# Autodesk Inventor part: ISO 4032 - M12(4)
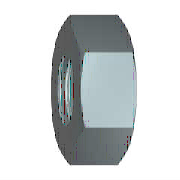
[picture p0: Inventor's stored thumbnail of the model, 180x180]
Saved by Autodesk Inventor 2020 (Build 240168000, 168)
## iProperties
Created: 2019-01
Part Number: ISO 4032 - M12(4)
Material: Nerezová ocel 440C
Description: Šestihranné matice, styl 1 – výrobní řada A a B
Document SubType Name: Modeling
Standard: ISO 4032
Designer: doma
Standard Revision: Fourth edition 2012-12-15
Standards Organization: ISO
Language: cs-CZ
Size Designation: M12
Categories: <MemberInstance><Categories><Category DisplayName="Spojovací materiál" InternalName="e4da775c-781d-43d5-af7c-5136215cf5a6" Mnemonic="FSTN"><Category DisplayName
Density: 7.75 g/cm^3
Appearance: Pololeštěná
Mass: 16.2537 g
Surface Area: 13.2759 cm^2
Volume: 2.09725 cm^3
IsCustomPart: 0
Author: doma
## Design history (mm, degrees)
sketch "Náčrt1"
  geometry: L1 (-10.392, 0)-(-5.196, 9); L2 (-5.196, 9)-(5.196, 9); L3 (5.196, 9)-(10.392, 0); L4 (10.392, 0)-(5.196, -9); L5 (5.196, -9)-(-5.196, -9); L6 (-5.196, -9)-(-10.392, 0); 2 further points
  constraints: 12 end point, 1 coincident, 1 horizontal, 11 other
  dimensions: "d0" = 20.78461 distance of L3.end L1.start (= 1.1547 x SW)
extrude "Těleso" new body sketch "Náčrt1" distance "d1" = 10.8 (= KOH); taper "d2" = 0 deg
sketch "Náčrt2"
  geometry: L1 (0, 5.196)-(0, 10.392) reference; L2 (0, 10.392)-(10.8, 10.392) reference; L3 (10.8, 5.196)-(10.8, 10.392) reference; L4 (-2.16, 0)-(12.96, 0) reference; L5 (1.208, 10.392)-(0, 8.3); L6 (9.592, 10.392)-(10.8, 8.3)
  constraints: 4 end point, 4 point on line
  dimensions: "d3" = 30 deg angle of L1 L5 (= ANG1); "d4" = 30 deg angle of L3 L6 (= ANG2); "d5" = 16.6 diameter of L5.end L4 (= SW0); "d6" = 16.6 diameter of L6.end L4 (= SW01)
revolve "Zkosení1" sketch "Náčrt2" stored, may be unused: angle "d7" = 90 deg
sketch "Náčrt3"
  geometry: 4 further points
  constraints: 1 coincident, 1 other
hole "Závit" sketch "Náčrt3" at (0, 0) diameter "d25" = 10.106; stored, may be unused: countersink angle "d29" = 82 deg, drill point angle "d31" = 118 deg; dims "d26" = 6, "d27" = 4, "d28" = 2, "d30" = 8
workaxis "Work Axis1"
workplane "Work Plane1"
body "Solid1"
chamfer "Zkosení2" distance "d8" = 0.94722 (= -0.5 x GD1 + 0.5 x NND); stored, may be unused: angle "d9" = 30 deg, second distance "d40" = 0.94722 (= -0.5 x GD1 + 0.5 x NND)
chamfer "Zkosení3" distance "d10" = 0.94722 (= -0.5 x GD1 + 0.5 x NND); stored, may be unused: angle "d11" = 30 deg, second distance "d41" = 0.94722 (= -0.5 x GD1 + 0.5 x NND)
other parameters: "ANG1" = 30 deg [user parameter; used in 1 equation term], "ANG2" = 30 deg [user parameter; used in 1 equation term], "NND" = 12 [user parameter; used in 4 equation terms], "KOH" = 10.8 [user parameter; used in 1 equation term], "SW" = 18 [user parameter; used in 2 equation terms], "SW0" = 16.6 [user parameter; used in 2 equation terms], "SW01" = 16.6 (= SW0) [user parameter; used in 1 equation term], "GD1" = 10.10557 (computed from THREADDIA, PTC, TOA) [user parameter; used in 4 equation terms], "d13" = 0, "d14" = 0, "d39" = 0, "d42" = 0, "GUL" = 0.94722 (= 0.541266 x PTC) [user parameter], "TPU" = 5.71429 (computed from PTC) [user parameter], "THREADDIA" = 12 [user parameter; used in 1 equation term], "TOA" = 30 deg [user parameter; used in 1 equation term], "PTC" = 1.75 [user parameter; used in 4 equation terms], "E0" = 20.79 (= 1.155 x SW) [user parameter], "GAL" = 0.94722 (= 0.541266 x PTC) [user parameter]
